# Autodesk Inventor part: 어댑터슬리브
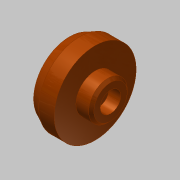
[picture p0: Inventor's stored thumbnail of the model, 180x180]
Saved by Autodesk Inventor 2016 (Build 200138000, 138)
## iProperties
Created: 2016-06
Part Number: 어댑터슬리브
Material: 강철, 탄소
Document SubType Name: Modeling
Designer: mduedu
Density: 7.87 g/cm^3
Appearance: 매끄러움 - 연한 주황색
Mass: 51.2566 g
Surface Area: 31.9511 cm^2
Volume: 6.51291 cm^3
Author: mduedu
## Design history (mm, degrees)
sketch "스케치2"
  geometry: L1 (0, 0)-(0, 14); L2 (0, 14)-(-4, 16); L3 (-4, 16)-(-10, 16); L4 (-10, 16)-(-10, 7.5); L5 (-10, 7.5)-(-16, 7.5); L6 (-16, 7.5)-(-16, 0); L7 (-16, 0)-(0, 0)
  constraints: 14 end point, 4 parallel, 1 perpendicular, 1 vertical
  dimensions: "d0" = 32 diameter of L3 L7; "d2" = 28 diameter of L1.end L7; "d3" = 6 distance of L2.end L3.end; "d4" = 6 distance of L4.end L5.end; "d5" = 15 diameter of L5 L7; "d6" = 16 distance between parallel lines of L6 L1
revolve "회전1" sketch "스케치2" stored, may be unused: angle "d7" = 90 deg
sketch "스케치3"
  geometry: L1 (-16, -7.5)-(-16, 7.5) reference; L2 (-16, 7.5)-(-10, 7.5) reference; L3 (-10, 7.5)-(-10, 16) reference; L4 (-10, 16)-(-4, 16) reference; L5 (-4, 16)-(0, 14) reference; L6 (0, 14)-(0, -14) reference; L7 (0, -14)-(-4, -16) reference; L8 (-4, -16)-(-10, -16) reference; L9 (-10, -16)-(-10, -7.5) reference; L10 (-10, -7.5)-(-16, -7.5) reference; L11 (0, 10)-(-5, 10); L12 (-5, 10)-(-5, 8); L13 (-5, 8)-(-7, 6); L14 (-7, 6)-(-7, 0); L15 (-7, 0)-(0, 0); L16 (0, 10)-(0, 0)
  constraints: 12 end point, 3 parallel, 2 perpendicular, 1 point on line
  dimensions: "d8" = 20 diameter of L11 L15; "d10" = 16 diameter of L12.end L15; "d11" = 12 diameter of L13.end L15; "d12" = 9 distance between parallel lines of L14 L1; "d13" = 2 distance between parallel lines of L12 L14
revolve "회전2" sketch "스케치3" stored, may be unused: angle "d14" = 90 deg
chamfer "모따기1" distance "d15" = 1; stored, may be unused: second distance "d16" = 2, angle "d17" = 45 deg
sketch "스케치4"
  geometry: 2 further points
  constraints: 1 coincident
sketch "스케치5"
  geometry: 1 further point
hole "구멍1" sketch "스케치5" at (0, 0) diameter "d18" = 4.5; stored, may be unused: countersink angle "d22" = 90 deg, drill point angle "d24" = 0 deg; dims "d19" = 6, "d20" = 8, "d21" = 4.6, "d23" = 8
node "솔리드1"
node "절단 모서리 투영1"
